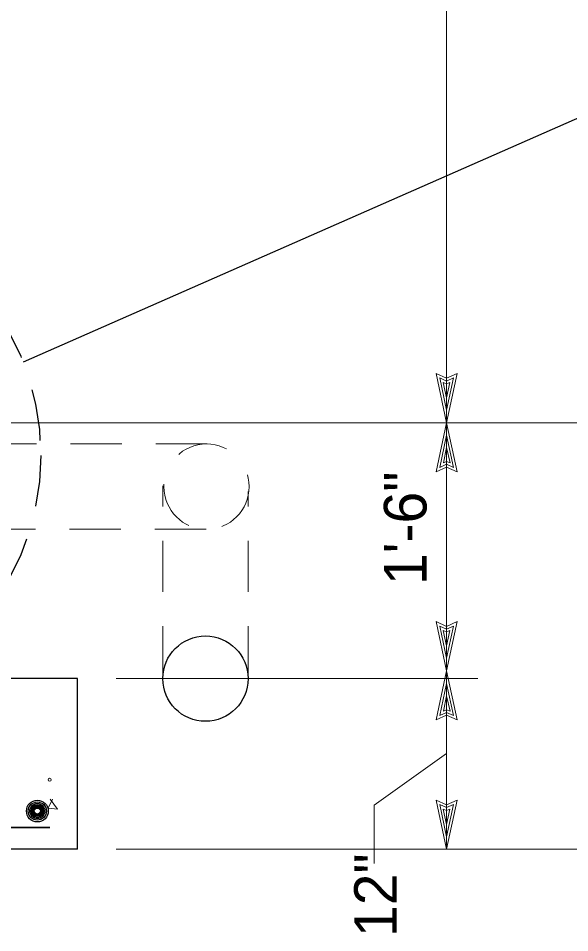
# Model space of a CAD drawing. Extents: x -24.3 to 17.7, y -17.6 to 12.4.
# Drawn here: x -2.791 to -1.175, y -12.761 to -10.082 of the extents above; entities that cross this region are included whole.
import ezdxf
from ezdxf.enums import TextEntityAlignment as Align

# ---------------------------------------------------------------- set-up
doc = ezdxf.new("R2010")
doc.units = 0
doc.header["$LTSCALE"] = 0.05
doc.linetypes.add('MEDIUM_DASHED', pattern=[4.5, 3, -1.5])
doc.layers.add('1', color=7, linetype='Continuous', lineweight=13)
doc.layers.add('2', color=7, linetype='Continuous', lineweight=13)

msp = doc.modelspace()

# ---------------------------------------------------------------- linework, layer by layer
at = {"layer": '1', "lineweight": 25}
for p, q in [((-0.69869, -10.1756), (-2.77669, -11.0896)), ((-2.61769, -12.0166), (-4.24269, -12.0166)), ((-2.61769, -12.5166), (-2.61769, -12.0166))]:
    msp.add_line(p, q, dxfattribs=at)
at = {"layer": '1'}
for p, q in [((-1.53569, -11.2666), (-1.56669, -11.1226)), ((-1.53569, -11.2296), (-1.55569, -11.1356)), ((-1.55569, -11.1356), (-1.53569, -11.1446)), ((-1.53569, -11.2666), (-1.50469, -11.1226)), ((-1.53569, -11.2296), (-1.51569, -11.1356)), ((-1.53569, -11.1446), (-1.51569, -11.1356)), ((-1.53569, -11.1936), (-1.54569, -11.1486)), ((-1.54569, -11.1486), (-1.53569, -11.1526)), ((-1.53569, -11.1936), (-1.52669, -11.1486)), ((-1.53569, -11.1526), (-1.52669, -11.1486)), ((-3.23169, -11.2666), (-0.82769, -11.2666)), ((-1.53569, -11.2666), (-1.56669, -11.4106)), ((-1.53569, -11.2666), (-1.50469, -11.4106)), ((-1.53569, -11.3036), (-1.55569, -11.3976)), ((-1.53569, -11.3036), (-1.51569, -11.3976)), ((-1.53569, -11.3396), (-1.54469, -11.3846)), ((-1.53569, -11.3396), (-1.52569, -11.3846)), ((-1.53569, -11.3806), (-1.54469, -11.3846)), ((-1.52569, -11.3846), (-1.53569, -11.3806)), ((-1.53569, -11.3886), (-1.55569, -11.3976)), ((-1.51569, -11.3976), (-1.53569, -11.3886)), ((-1.53569, -11.9936), (-1.56669, -11.8496)), ((-1.53569, -11.9566), (-1.55569, -11.8626)), ((-1.55569, -11.8626), (-1.53569, -11.8716)), ((-1.53569, -11.9936), (-1.50469, -11.8496)), ((-1.53569, -11.9566), (-1.51569, -11.8626)), ((-1.53569, -11.8716), (-1.51569, -11.8626)), ((-1.53569, -11.9206), (-1.54569, -11.8756)), ((-1.54569, -11.8756), (-1.53569, -11.8796)), ((-1.53569, -11.9206), (-1.52669, -11.8756)), ((-1.53569, -11.8796), (-1.52669, -11.8756)), ((-1.53569, -11.9936), (-1.56669, -12.1376)), ((-1.53569, -11.9936), (-1.50469, -12.1376)), ((-2.50469, -12.0166), (-1.44469, -12.0166)), ((-1.53569, -12.0306), (-1.55569, -12.1246)), ((-1.53569, -12.0306), (-1.51569, -12.1246)), ((-1.53569, -12.0666), (-1.54469, -12.1116)), ((-1.53569, -12.0666), (-1.52569, -12.1116)), ((-1.53569, -12.1076), (-1.54469, -12.1116)), ((-1.52569, -12.1116), (-1.53569, -12.1076)), ((-1.53569, -12.1156), (-1.55569, -12.1246)), ((-1.51569, -12.1246), (-1.53569, -12.1156)), ((-1.53569, -12.5166), (-1.56669, -12.3726)), ((-1.53569, -12.5166), (-1.50469, -12.3726)), ((-1.53569, -12.4796), (-1.55569, -12.3856)), ((-1.55569, -12.3856), (-1.53569, -12.3946)), ((-1.53569, -12.4436), (-1.54569, -12.3986)), ((-1.54569, -12.3986), (-1.53569, -12.4026)), ((-1.53569, -12.4796), (-1.51569, -12.3856)), ((-1.53569, -12.3946), (-1.51569, -12.3856)), ((-1.53569, -12.4436), (-1.52669, -12.3986)), ((-1.53569, -12.4026), (-1.52669, -12.3986)), ((-2.50469, -12.5166), (-0.82769, -12.5166))]:
    msp.add_line(p, q, dxfattribs=at)
at = {"layer": '1', "linetype": 'MEDIUM_DASHED'}
for p, q in [((-2.23769, -11.3286), (-3.25769, -11.3286)), ((-2.36769, -12.0126), (-2.36769, -11.4516)), ((-2.11769, -12.0126), (-2.11769, -11.4686)), ((-2.24069, -11.5786), (-3.11769, -11.5786))]:
    msp.add_line(p, q, dxfattribs=at)
at = {"layer": '1', "lineweight": 35}
msp.add_line((-3.63269, -12.4526), (-2.69869, -12.4526), dxfattribs=at)
at = {"layer": '1'}
for points in [[(-1.53569, -12.5166), (-1.53569, -11.9936), (-1.53569, -11.2666), (-1.53569, -8.0586), (-1.53569, -4.0576)], [(-1.56669, -11.1226), (-1.53569, -11.1366), (-1.50469, -11.1226)], [(-1.50469, -11.4106), (-1.53569, -11.3966), (-1.56669, -11.4106)], [(-1.56669, -11.8496), (-1.53569, -11.8636), (-1.50469, -11.8496)], [(-1.50469, -12.1376), (-1.53569, -12.1236), (-1.56669, -12.1376)], [(-1.74769, -12.5586), (-1.74769, -12.3876), (-1.53569, -12.2356)], [(-1.56669, -12.3726), (-1.53569, -12.3866), (-1.50469, -12.3726)]]:
    msp.add_lwpolyline(points, dxfattribs=at)
at = {"layer": '1', "lineweight": 25}
msp.add_lwpolyline([(-2.61769, -12.5166), (-4.24269, -12.5166), (-4.24269, -12.0166)], dxfattribs=at)
at = {"layer": '1', "linetype": 'MEDIUM_DASHED', "lineweight": 25}
msp.add_circle((-3.47269, -11.3626), 0.7473, dxfattribs=at)
at = {"layer": '1', "linetype": 'MEDIUM_DASHED'}
msp.add_circle((-2.23952, -11.45406), 0.125, dxfattribs=at)
at = {"layer": '1', "lineweight": 25}
for centre, radius in [((-2.24252, -12.01663), 0.125), ((-2.73533, -12.40451), 0.0319), ((-2.73533, -12.40451), 0.02658), ((-2.73533, -12.40451), 0.02215), ((-2.73533, -12.40451), 0.01846), ((-2.73533, -12.40451), 0.01538), ((-2.73533, -12.40451), 0.01282), ((-2.73533, -12.40451), 0.01068), ((-2.73533, -12.40451), 0.0089)]:
    msp.add_circle(centre, radius, dxfattribs=at)
at = {"layer": '2'}
msp.add_lwpolyline([(-2.69069, -12.3696), (-2.70369, -12.3956), (-2.67669, -12.3986), (-2.69769, -12.3696)], dxfattribs=at)
msp.add_circle((-2.69922, -12.31279), 0.00433, dxfattribs=at)

# ---------------------------------------------------------------- texts
at = {"layer": '1'}
for s, p in [('1\'-6"', (-1.59469, -11.5761)), ('12"', (-1.68169, -12.6511))]:
    msp.add_text(s, height=0.125, rotation=90, dxfattribs=at).set_placement(p, align=Align.CENTER)

doc.saveas('drawing.dxf')
